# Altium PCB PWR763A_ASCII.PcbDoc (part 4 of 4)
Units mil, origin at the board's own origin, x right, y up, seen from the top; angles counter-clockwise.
Board outline 5000 x 7000 mil, 4 copper layers (Top Layer, Signal Layer 1, Signal Layer 2, Bottom Layer), stack 61.2 mil thick; 559 components, 281 nets, 1477 pads, 685 vias.
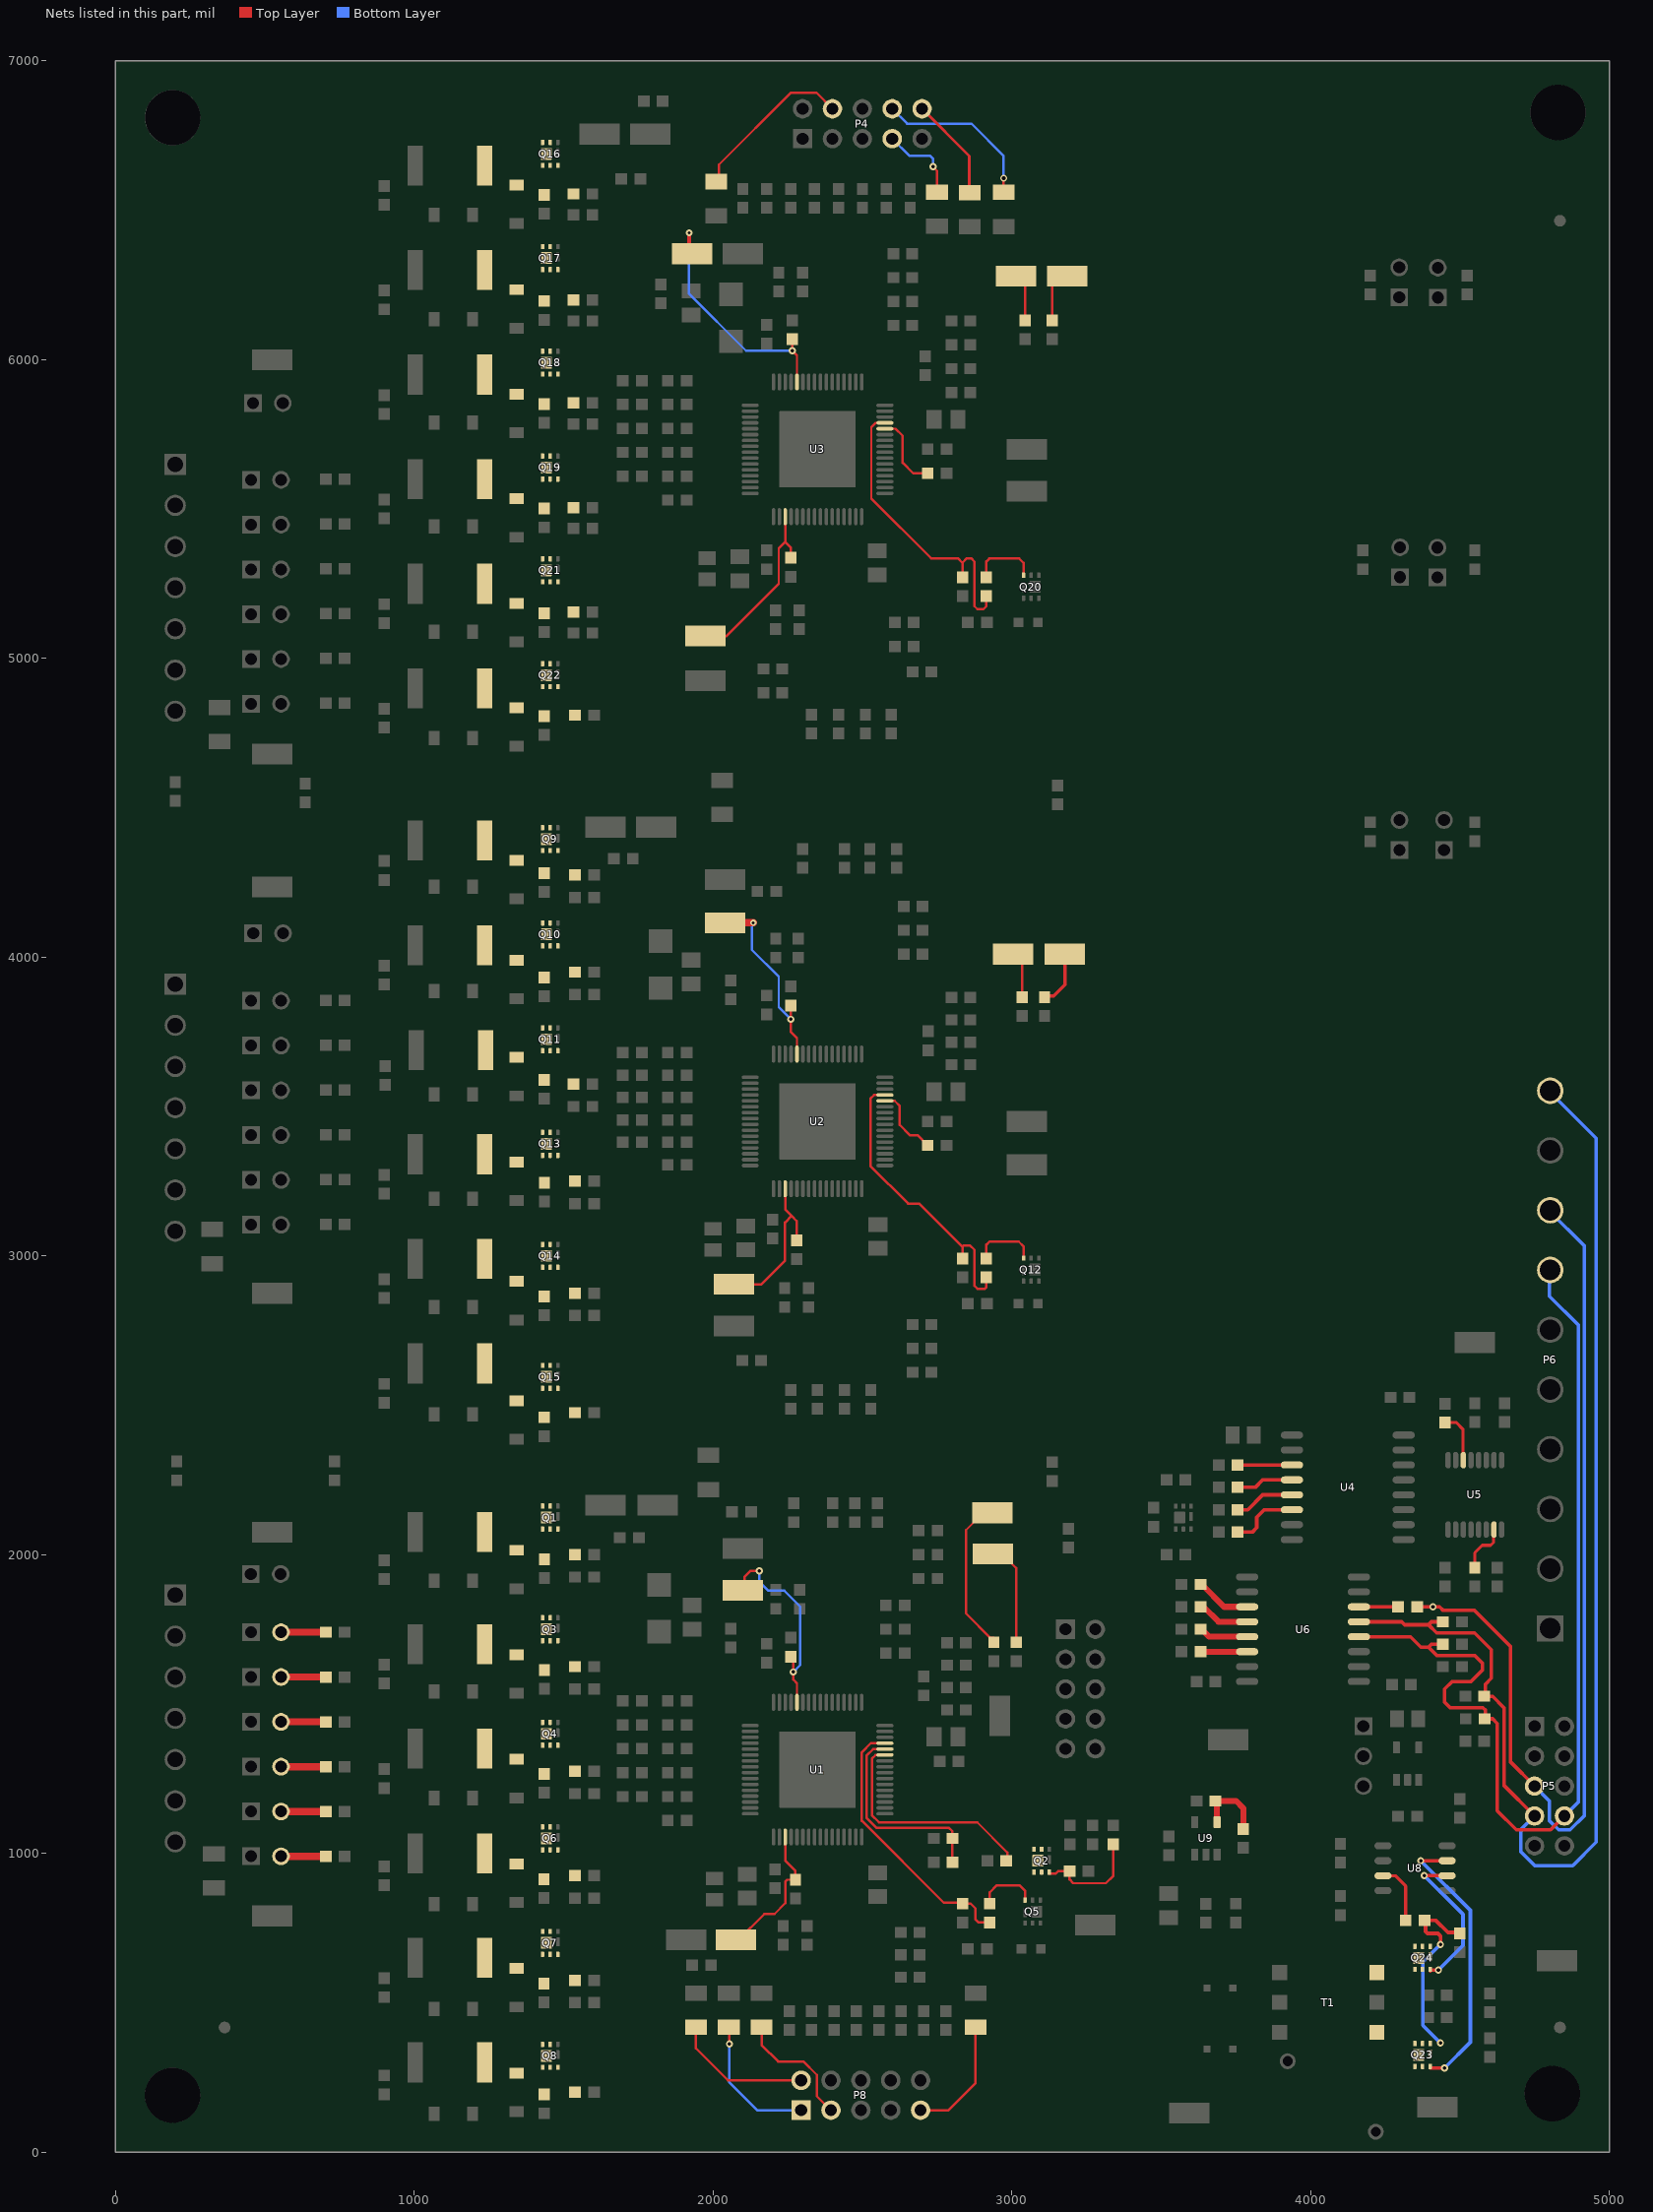
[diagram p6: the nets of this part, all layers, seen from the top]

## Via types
v1: diameter 24, hole 12, Top Layer to Bottom Layer, tented both sides, 607 vias
v2: diameter 19.68, hole 7.87, Top Layer to Bottom Layer, 75 vias
v3: diameter 22, hole 10, Top Layer to Bottom Layer, tented both sides, 3 vias

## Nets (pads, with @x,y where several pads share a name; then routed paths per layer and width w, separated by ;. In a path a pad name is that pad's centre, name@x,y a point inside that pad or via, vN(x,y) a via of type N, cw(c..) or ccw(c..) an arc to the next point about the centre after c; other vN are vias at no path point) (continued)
NetJP13_2: JP13.2 R47.1 | length 144
  Top Layer w24: JP13.2@556,1740 R47.1@700,1740
NetJP14_2: JP14.2 R48.1 | length 144
  Top Layer w24: JP14.2@556,1590 R48.1@700,1590
NetJP15_2: JP15.2 R49.1 | length 144
  Top Layer w24: JP15.2@556,1440 R49.1@700,1440
NetJP16_2: JP16.2 R50.1 | length 144
  Top Layer w24: JP16.2@556,1290 R50.1@700,1290
NetJP17_2: JP17.2 R51.1 | length 144
  Top Layer w24: JP17.2@556,1140 R51.1@700,1140
NetJP18_2: JP18.2 R52.1 | length 144
  Top Layer w24: JP18.2@556,990 R52.1@700,990
NetP4_4: P4.4 R1.2 | length 558.1
  Top Layer w8: R1.2@2020,6597.09 2020,6653 2261,6894 2346,6894 P4.4@2400,6840
NetP4_7: P4.7 R10.2 | length 281.6
  Top Layer w8: v1(2737,6646) 2737,6645 2750,6632 R10.2@2750,6561.09
  Bottom Layer w8: P4.7@2600,6740 2658,6682 2727.24,6682 2737,6672.24 v1(2737,6646)
NetP4_8: P4.8 R12.2 | length 560.8
  Top Layer w8: R12.2@2958.87,6560.9 R12.2@2959.06,6561.08 ; R12.2@2972.87,6559.9 2972.97,6560 v1(2972.97,6607.69)
  Bottom Layer w8: P4.8@2600,6840 2650,6790 2865,6790 2972.97,6682.03 v1(2972.97,6607.69)
NetP4_10: P4.10 R11.2 | length 346.6
  Top Layer w10: P4.10@2700,6840 2858,6682 2858,6561.72 R11.2@2860,6559.72
NetP8_1: P8.1 R55.1 | length 463.8
  Top Layer w8: R55.1@2053,417.4 2055,415.4 v1(2055,362)
  Bottom Layer w8: v1(2055,362) 2055,233 2148,140 P8.1@2295,140
NetP8_2: P8.2 R54.1 | length 467.7
  Top Layer w8: R54.1@1943,418.4 1943,347 2050,240 P8.2@2295,240
NetP8_3: P8.3 R56.1 | length 423.3
  Top Layer w8: R56.1@2163,417.4 2163,358 2218,303 2303,303 2348,258 2348,187 P8.3@2395,140
NetP8_9: P8.9 R65.1 | length 410.6
  Top Layer w8: P8.9@2695,140 2788,140 2879,231 R65.1@2879,419.91
NetQ1_1: Q1.1 Q1.2 Q1.5 Q1.6 Q1.8 R66.1
NetQ1_3: Q1.3 R69.2 R71.2 Z3.1
NetQ2_1: Q2.1 Q2.2 Q2.5 Q2.6 Q2.8 R70.1 U1.43 | length 773.8
  Top Layer w8: U1.43@2578.35,1329.21 2544.21,1329.21 2532,1317 2532,1127 2555.79,1103.21 2884.79,1103.21 2985,1003 R70.1@2985,975
NetQ2_3: Q2.3 R73.2 R75.2 | length 366.4
  Top Layer w8: Q2.3@3125.59,931.69 3146.69,931.69 3155,940 R75.2@3193.5,940 3193.5,912.5 3206,900 3315,900 3340,925 R73.2@3340,1030.5
NetQ3_1: Q3.1 Q3.2 Q3.5 Q3.6 Q3.8 R74.1
NetQ3_3: Q3.3 R76.2 R78.2 Z5.1
NetQ4_1: Q4.1 Q4.2 Q4.5 Q4.6 Q4.8 R81.1
NetQ4_3: Q4.3 R87.2 R90.2 Z7.1
NetQ5_3: Q5.3 R88.1 | length 198.9
  Top Layer w8: R88.1@2926,831.5 2926,869 2949,892 3027,892 3044.41,874.59 Q5.3@3044.41,848.31
NetQ6_1: Q6.1 Q6.2 Q6.5 Q6.6 Q6.8 R93.1
NetQ6_3: Q6.3 R95.2 R97.2 Z9.1
NetQ7_1: Q7.1 Q7.2 Q7.5 Q7.6 Q7.8 R100.1
NetQ7_3: Q7.3 R102.2 R107.2 Z11.1
NetQ8_1: Q8.1 Q8.2 Q8.5 Q8.6 Q8.8 R110.1
NetQ8_3: Q8.3 R111.2 R112.2 Z13.1
NetQ9_1: Q9.1 Q9.2 Q9.5 Q9.6 Q9.8 R113.1
NetQ9_3: Q9.3 R116.2 R117.2 Z16.1
NetQ10_1: Q10.1 Q10.2 Q10.5 Q10.6 Q10.8 R119.1
NetQ10_3: Q10.3 R120.2 R121.2 Z18.1
NetQ11_1: Q11.1 Q11.2 Q11.5 Q11.6 Q11.8 R124.1
NetQ11_3: Q11.3 R125.2 R129.2 Z20.1
NetQ12_3: Q12.3 R130.2 | length 206.2
  Top Layer w8: R130.2@2915,2995 2915,3037.37 2925.38,3047.75 3023.59,3047.75 3039.41,3031.92 3039.41,3003.31
NetQ13_1: Q13.1 Q13.2 Q13.5 Q13.6 Q13.8 R133.1
NetQ13_3: Q13.3 R136.2 R137.2 Z22.1
NetQ14_1: Q14.1 Q14.2 Q14.5 Q14.6 Q14.8 R139.1
NetQ14_3: Q14.3 R142.2 R143.2 Z24.1
NetQ15_1: Q15.1 Q15.2 Q15.5 Q15.6 Q15.8 R147.1
NetQ15_3: Q15.3 R148.2 R149.2 Z26.1
NetQ16_1: Q16.1 Q16.2 Q16.5 Q16.6 Q16.8 R150.1
NetQ16_3: Q16.3 R153.2 R154.2 Z29.1
NetQ17_1: Q17.1 Q17.2 Q17.5 Q17.6 Q17.8 R156.1
NetQ17_3: Q17.3 R157.2 R158.2 Z31.1
NetQ18_1: Q18.1 Q18.2 Q18.5 Q18.6 Q18.8 R160.1
NetQ18_3: Q18.3 R162.2 R163.2 Z33.1
NetQ19_1: Q19.1 Q19.2 Q19.5 Q19.6 Q19.8 R167.1
NetQ19_3: Q19.3 R173.2 R174.2 Z35.1
NetQ20_3: Q20.3 R171.2 | length 220.6
  Top Layer w8: R171.2@2915,5275 2915,5324.41 2925,5334.41 3025,5334.41 3039.41,5320 Q20.3@3039.41,5283.31
NetQ21_1: Q21.1 Q21.2 Q21.5 Q21.6 Q21.8 R176.1
NetQ21_3: Q21.3 R178.2 R180.2 Z37.1
NetQ22_1: Q22.1 Q22.2 Q22.5 Q22.6 Q22.8 R183.1
NetQ22_3: Q22.3 R186.2 R187.2 Z39.1
NetQ23_1: Q23.1 Q23.2 Q23.5 Q23.6 Q23.8 T1.1
NetQ23_3: Q23.3 U8.7 | length 922.3
  Top Layer w12: v1(4369.02,975.07) 4444,975.07 U8.7@4444,975 ; Q23.3@4400.59,281.69 4400.59,280.93 v1(4448.21,280.93)
  Bottom Layer w12: v1(4369.02,975.07) 4535,809.09 4535,367.71 v1(4448.21,280.93)
NetQ23_4: Q23.4 Q23.7 Q24.4 Q24.7 R214.2 R215.2 | length 631.6
  Top Layer w12: v1(4435,695) 4435,723.29 4426.44,731.85 4391.6,731.85 4385,738.45 4385,775 4420,775 4460,735 R215.2@4500,735
  Bottom Layer w12: v1(4435,365) 4376,424 4376,636 v1(4435,695)
NetQ24_1: Q24.1 Q24.2 Q24.5 Q24.6 Q24.8 T1.3
NetQ24_3: Q24.3 U8.6 | length 498.3
  Top Layer w12: v1(4380.63,925.58) 4444,925.58 U8.6@4444,925 ; Q24.3@4400.59,606.69 4400.59,608.93 v1(4428.21,608.93)
  Bottom Layer w12: v1(4380.63,925.58) 4510.48,795.73 4510.48,691.19 v1(4428.21,608.93)
NetR86_1: R86.1 R88.2 U1.45 | length 909.8
  Top Layer w8: U1.45@2575.39,1368.58 2528.58,1368.58 2498,1338 2498,1109 2772,835 2831.5,835 R86.1@2835,831.5 2862.5,831.5 2879,815 2879,778 2888.5,768.5 R88.2@2926,768.5
NetR89_1: R89.1 TP-3.1 U1.19 | length 481.9
  Top Layer w8: TP-3.1@2077,710 2085,710 2172,797 2206,797 2242,833 2242,905 2248.5,911.5 R89.1@2276,911.5 2276,941 2241.73,975.27 U1.19@2241.73,1054.61
NetR91_1: R91.1 TP-1.1 U1.60 | length 695.5
  Top Layer w8: TP-1.1@2105,1885 2105,1925 2125,1945 v1(2155,1945) ; R91.1@2260,1658.5 2269,1649.5 v1(2269,1607) 2269,1581 2281.1,1568.9 U1.60@2281.1,1505.39
  Bottom Layer w8: v1(2155,1945) 2155,1910 2186,1879 2239,1879 2292,1826 2292,1630 v1(2269,1607)
NetR94_1: R94.1 R96.2 U1.44 | length 688.3
  Top Layer w8: U1.44@2575.39,1348.9 2535.9,1348.9 2514,1327 2514,1119 2548.29,1084.71 2790.29,1084.71 2801.5,1073.5 R96.2@2801.5,1050 R94.1@2801.5,970
NetR99_2: R99.2 TP-5.1 | length 496.9
  Top Layer w8: TP-5.1@2900,2140 2900,2135 2847,2082 2847,1803 2929,1721 2940,1721 R99.2@2940,1710
NetR106_2: R106.2 TP-6.1 | length 380.7
  Top Layer w8: TP-6.1@2900,2005 2965,2005 3015,1955 R106.2@3015,1710
NetR126_1: R126.1 R130.1 U2.45 | length 981.3
  Top Layer w8: U2.45@2578.35,3538.58 2539.58,3538.58 2527,3526 2527,3301 2653,3175 2690,3175 2835,3030 ; R126.1@2835,2995 2835,3030 ; R130.1@2915,2925 2915,2895 2910,2890 2885,2890 2875,2900 2875,3020 2860,3035 2840,3035 2835,3030
NetR132_1: R132.1 TP-9.1 U2.19 | length 545.2
  Top Layer w8: TP-9.1@2070,2905 2162.27,2905 2241.14,2983.87 2241.14,3111.62 2263.19,3133.67 ; U2.19@2241.73,3221.65 2241.73,3155.12 2263.19,3133.67 ; R132.1@2280,3055 2280,3116.85 2263.19,3133.67
NetR134_1: R134.1 TP-7.1 U2.60 | length 640.2
  Top Layer w8: R134.1@2260,3835 2260.79,3835 v1(2260.79,3791.93) 2260.79,3749.14 2281.1,3728.82 U2.60@2281.1,3678.35
  Top Layer w24: TP-7.1@2040,4115 v3(2135,4115)
  Bottom Layer w8: v3(2135,4115) 2130,4110 2130,4025 2220,3935 2220,3832.72 v1(2260.79,3791.93)
NetR135_1: R135.1 U2.44 | length 242.3
  Top Layer w8: U2.44@2575.39,3518.9 2608.1,3518.9 2625,3502 2625,3438 2659,3404 2684.5,3404 R135.1@2718.5,3370
NetR140_2: R140.2 TP-11.1 | length 140
  Top Layer w8: R140.2@3035,3870 TP-11.1@3035,4010
NetR144_2: R144.2 TP-12.1 | length 185.7
  Top Layer w12: R144.2@3110,3870 3140,3870 3178,3908 TP-12.1@3178,4010
NetR168_1: R168.1 R171.1 U3.45 | length 1014.3
  Top Layer w8: U3.45@2575.39,5788.58 2545,5788.58 2530,5773.58 2530,5535 2730,5335 2820,5335 2835,5320 ; R168.1@2835,5271.5 2835,5320 ; R171.1@2915,5208.5 2915,5175 2905,5165 2885,5165 2875,5175 2875,5324 2864,5335 2850,5335 2835,5320
NetR169_1: R169.1 TP-15.1 U3.19 | length 605.7
  Top Layer w8: TP-15.1@1975,5075 2045,5075 2220,5250 2220,5368.27 2241.73,5390 ; U3.19@2241.73,5471.65 2241.73,5390 ; R169.1@2260,5340 2260,5371.73 2241.73,5390
NetR170_1: R170.1 TP-13.1 U3.60 | length 846.1
  Top Layer w8: R170.1@2265,6065 v1(2265,6030) 2281.1,6013.9 U3.60@2281.1,5928.35
  Top Layer w12: v3(1920,6425) 1920,6365.75 TP-13.1@1930.75,6355
  Bottom Layer w8: v3(1920,6425) 1920,6220.59 2110.59,6030 v1(2265,6030)
NetR172_1: R172.1 U3.44 | length 257.5
  Top Layer w8: U3.44@2575.39,5768.9 2611.1,5768.9 2635,5745 2635,5655 2670,5620 R172.1@2718.5,5620
NetR179_2: R179.2 TP-17.1 | length 145
  Top Layer w8: R179.2@3045,6135 TP-17.1@3045,6280
NetR184_2: R184.2 TP-18.1 | length 177.4
  Top Layer w8: R184.2@3135,6135 3135,6250 3165,6280 TP-18.1@3185,6280
NetR188_2: R188.2 U4.3 | length 175.6
  Top Layer w12: R188.2@3760,2300 3760.1,2299.9 U4.3@3935.6,2299.9
NetR189_2: R189.2 U4.4 | length 185.9
  Top Layer w12: R189.2@3760,2225 3815.1,2225 3840,2249.9 U4.4@3935.6,2249.9
NetR190_1: R190.1 U5.6 | length 182
  Top Layer w10: R190.1@4450,2442.5 4487.5,2442.5 4510,2420 U5.6@4510,2307.3
NetR193_2: R193.2 U4.5 | length 196.3
  Top Layer w12: R193.2@3760,2150 3790.1,2150 3840,2199.9 U4.5@3935.6,2199.9
NetR194_2: R194.2 U4.6 | length 227.1
  Top Layer w12: R194.2@3760,2075 3805.1,2075 3820.1,2090 3820.1,2125 3845,2149.9 U4.6@3935.6,2149.9
NetR195_1: R195.1 U5.15 | length 174
  Top Layer w10: R195.1@4550,1956.5 4550,2006 4575,2031 4603,2031 4612.3,2040.3 U5.15@4612.3,2088.3
NetR197_1: R197.1 U6.14 | length 156.5
  Top Layer w20: R197.1@3631.5,1675 U6.14@3787.99,1675
NetR201_1: R201.1 U6.13 | length 166.9
  Top Layer w20: R201.1@3631.5,1750 3636,1750 3661,1725 U6.13@3787.99,1725
NetR203_1: R203.1 U6.12 | length 177.2
  Top Layer w20: R203.1@3631.5,1825 3642,1825 3692,1775 U6.12@3787.99,1775
NetR205_2: R205.2 U6.6 | length 131.5
  Top Layer w12: U6.6@4162.01,1825 R205.2@4293.5,1825
NetR206_1: R206.1 U6.11 | length 187.6
  Top Layer w20: R206.1@3631.5,1900 3636,1900 3711,1825 U6.11@3787.99,1825
NetR212_2: R212.2 R213.2 U9.4 | length 244
  Top Layer w20: R212.2@3681.5,1175 3751,1175 3775,1151 R213.2@3775,1081.5 ; R212.2@3687,1175 3687,1104.54 U9.4@3687.4,1104.13
NetR214_1: R214.1 U8.3 | length 193.3
  Top Layer w10: U8.3@4255,925 4284,925 4318.5,890.5 R214.1@4318.5,775
SCLK: P5.7 P6.10 R200.1 R209.2 U6.5 | length 4197.6
  Top Layer w12: U6.5@4164.4,1775.1 4164.5,1775 4305,1775 4315,1765 4395,1765 ; R200.1@4440,1775 4405,1775 4395,1765 ; P5.7@4750,1125 4647.48,1227.52 4647.48,1487.52 4610,1525 4585,1525 4585,1565.86 4605,1585.86 4605,1681.77 4549.27,1737.5 4422.5,1737.5 4395,1765
  Bottom Layer w12: P5.7@4750,1125 4703.5,1078.5 4703.5,1005.74 4750.74,958.5 4877.55,958.5 4956.5,1037.45 4956.5,3393.5 P6.10@4800,3550
SIMO: P5.8 P6.7 R199.1 R208.2 U6.4 | length 3387.4
  Top Layer w12: U6.4@4164.4,1725.1 4164.5,1725 4335,1725 4370,1690 4395,1690 ; R199.1@4440,1700 4405,1700 4395,1690 ; P5.8@4850,1125 4803.5,1078.5 4688.89,1078.5 4625,1142.39 4625,1435 4610,1450 4585,1450 4585,1480 4577.5,1487.5 4467.5,1487.5 4449,1506 4449,1550 4474,1575 4536.77,1575 4576,1614.23 4576,1635.77 4549.27,1662.5 4422.5,1662.5 4395,1690
  Bottom Layer w12: P6.7@4800,2950 4800,2865.25 4896.5,2768.75 4896.5,1171.5 P5.8@4850,1125
SOMI: P5.5 P6.8 R205.1 | length 3222.9
  Top Layer w12: R205.1@4360,1825 v1(4410,1825) 4432.62,1825 4444.62,1813 4548.77,1813 4670,1691.77 4670,1305 P5.5@4750,1225
  Bottom Layer w12: P5.5@4750,1225 4800,1175 4800,1109.24 4830.74,1078.5 4869.26,1078.5 4916.5,1125.74 4916.5,3033.5 P6.8@4800,3150
pads on no net: FID1.1 FID2.1 FID3.1 H1. H2. H3. H4. LBL1.0 P7.3 P7.4 P7.6 SH-J1.0 SH-J2.0 SH-J3.0 SH-J4.0 SH-J5.0 SH-J6.0 SH-J7.0 SH-J8.0 SH-JP1.0 SH-JP2.0 SH-JP3.0 SH-JP4.0 SH-JP5.0 SH-JP6.0 SH-JP7.0 SH-JP8.0 SH-JP9.0 SH-JP10.0 SH-JP11.0 SH-JP12.0 SH-JP13.0 SH-JP14.0 SH-JP15.0 SH-JP16.0 SH-JP17.0 SH-JP18.0 SH-JP19.0 U1.30 U1.31 U1.51 U1.62 U2.30 U2.31 U2.36 U2.37 U2.38 U2.39 U2.40 U2.41 U2.42 U2.43 U2.51 U2.62 U3.30 U3.31 U3.36 U3.37 U3.38 U3.39 U3.40 U3.41 U3.42 U3.43 U3.51 U3.62 U7.4 U8.1
copper on no net: | length 43.5
  Top Layer w20: v1(1805,5450) 1848.5,5450

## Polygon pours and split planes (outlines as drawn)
2-VC0 on Bottom Layer "Bottom-2-VSS" (solid, remove dead copper, pour order 21): 50,4500 50,2300 2250,2300 2250,1475 2629,1475 2629,2300 3250,2300 3400,2450 3400,4500 2650,4500 2650,3625 2250,3625 2250,4500
3-VC0 on Bottom Layer "Bottom-3-VSS" (solid, remove dead copper, pour order 22): 50,6950 50,4575 2275,4575 2275,3650 2625,3650 2625,4575 3390,4575 3390,6950
1-VC0 on Bottom Layer "Bottom-1-VSS" (solid, remove dead copper, pour order 24): 50,2250 50,50 4015,50 4015,2435 3545,2435 3465,2355 3465,2350 3365,2250 2625,2250 2625,1450 2225,1450 2225,2250
2-VC0 on Top Layer "Top-2-VSS" (solid, remove dead copper, pour order 16): 50,4500 50,2300 2250,2300 2250,1475 2600,1475 2600,2300 3400,2300 3400,4500 2650,4500 2650,3625 2250,3625 2250,4500
1-VC0 on Top Layer "Top-1-VSS" (solid, remove dead copper, pour order 19): 50,2250 50,50 4015,50 4015,2435 3545,2435 3465,2355 3465,2350 3365,2250 2625,2250 2625,1450 2225,1450 2225,2250
3-VC0 on Top Layer "Top-3-VSS" (solid, remove dead copper, pour order 18): 50,6950 50,4575 2275,4575 2275,3650 2625,3650 2625,4575 3390,4575 3390,6950
2-VC0 on Signal Layer 1 "Signal Layer 2-No Net 1" (solid, remove dead copper, pour order 20): 50,4500 3400,4500 3400,2450 3250,2300 50,2300
1-VC0 on Signal Layer 1 "Signal Layer 2-No Net 2" (solid, remove dead copper, pour order 23): 50,2250 3400,2250 3400,50 50,50
NetC120_1 on Signal Layer 1 "Signal Layer 2-No Net 3" (solid, remove dead copper, pour order 25): 3460,2350 3545,2435 4010,2435 4010,50 3460,50 3460,2325
3.3_SW on Signal Layer 1 "Signal Layer 2-No Net 4" (solid, remove dead copper, pour order 26): 4075,2990 4675,2990 4675,3725 4965,3725 4965,50 4065,50 4065,2990
AGND on Signal Layer 1 "Signal Layer 2-No Net" (solid, pour order 17): 50,6950 3390,6950 3390,4580 3385,4575 50,4575
3-VC0 on Signal Layer 2 "Signal Layer 1-No Net" (solid, remove dead copper, pour order 27): 50,6950 3390,6950 3400,6940 3400,4575 2625,4575 2625,3650 2276.77,3650 2276.77,4575 50,4575
2-VC0 on Signal Layer 2 "Signal Layer 1-No Net 1" (solid, remove dead copper, pour order 28): 50,4500 2250,4500 2250,3625 2650,3625 2650,4500 3400,4500 3400,2445 3255,2300 3250,2300 2600,2300 2600,1475 2251.46,1475 2250,1476.46 2250,2300 50,2300
1-VC0 on Signal Layer 2 "Signal Layer 1-No Net 2" (solid, remove dead copper, pour order 29): 50,2250 2200,2250 2225,2250 2225,1450 2625,1450 2625,2250 3365,2250 3545,2430 3545,2435 4015,2435 4015,2370 4015,50 3830,50 50,50
AGND on Signal Layer 2 "Signal Layer 1-No Net 3" (solid, remove dead copper, pour order 30): 4065,2990 4675,2990 4675,3735 4965,3735 4965,35 4065,35 4065,2990 4675,2990 4675,3735 4675,2990

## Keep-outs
Keep-Out Layer:
  text ".Layer_Name" at 577,-858.49 h60

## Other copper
Top Layer:
  text ".Layer_Name" at 577,-858.49 h60
Signal Layer 1:
  text ".Layer_Name" at 577,-858.49 h60
Signal Layer 2:
  text ".Layer_Name" at 577,-858.49 h60
Bottom Layer:
  text ".Layer_Name" at 577,-858.49 h60

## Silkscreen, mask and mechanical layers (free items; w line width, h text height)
Top Overlay:
  lines w5: 1615,3679 1655,3639 ; 1620,5700 1642,5722 1642,5733 1655,5746 ; 1624,3637 1642,3619 1642,3593 1649,3586 1649,3559 1656,3552 ; 1630,5655 1660,5684
  lines w6: 1626,5936 1627,5936 1644,5919 1644,5867 1660,5851 ; 2563,626 2581,608 2590,608
  lines w8: 3010,5035 3030,5035 ; 3020,2710 3040,2710 ; 3025,560 3045,560 ; 3065,5005 3065,5035 ; 3065,5065 3065,5035 ; 3075,2680 3075,2710 ; 3075,2740 3075,2710 ; 3080,530 3080,560 ; 3080,590 3080,560 ; 3100,5035 3065,5035 ; 3110,2710 3075,2710 ; 3115,560 3080,560 ; 4019.6,58.56 4019.6,1033.56 ; 4019.6,1233.56 4019.6,2833.56 ; 4049.6,58.56 4049.6,1033.56 ; 4070,1235 4070,2835 ; 4635,3005 4635,3685 ; 3065,5035 3035,5005 3035,5065 3065,5035 ; 3075,2710 3045,2680 3045,2740 3075,2710 ; 3080,560 3050,530 3050,590 3080,560
  lines w10: 1515,2255 820,2255 820,40 2065,40 ; 1525,4505 1480,4505 820,4505 820,2295 1515,2295 1870,2295 ; 1700,6895 818.3,6895 818.3,4570.8 1919.2,4570.8 ; 1885,6895 2055,6895 ; 2065,2255 2235,2255 ; 2065,2295 3035,2295 ; 2105,4500 3050,4500 ; 2105,4575 3050,4575 ; 2590,2255 3035,2255 ; 2920,40 3400,40 3400,1080 ; 3020,6900 3400,6900 3400,4575.8 3205.8,4575.8 ; 3178.89,2250 3200,2250 3400,2250 3400,2005 ; 3180,2295 3399.2,2295 ; 3205,4500 3400,4500 3400,2445 3400,2294.2 ; 4965,40 3425,40 3425,3005 4630,3005 4630,3690 4965,3690 ; 4000,4015 4800,4015 4800,4665 4000,4665 4000,4015 ; 4000,4880 4800,4880 4800,5530 4000,5530 4000,4880 ; 4000,5750 4800,5750 4800,6425 4000,6425 4000,5750
  text "2" at 2062.56,6837.64 h25
  text "10" at 2917.27,6834.64 h25
  text "9" at 2921.77,6735.68 h25
  text "1" at 2070.06,6720.68 h25
  text "Bq76PL536A-Q1 EVM-3" at 3618,6549 h100
  text "PWR763A" at 4195,6440 h100
  text "TS2+" at 2190,6340 h45
  text "TS2-" at 1730,6335 h45
  text "CAUTION" at 245,6260 h100
  text "HIGH VOLTAGE" at 117,6149 h100
  text "JUMPERS" at 130,5995 h50
  text "THERMISTORS CIRCUIT 3" at 4065,5980 h40
  text "THERMISTORS" at 4145,5790 h50
  text "1" at 195.7,5776.01 h50
  text "CELL 18+" at 292,5658 h35
  text "CELL 17+" at 291,5509 h35
  text "CELL 16+" at 291,5359 h35
  text "CELL 15+" at 290,5210 h35
  text "THERMISTORS CIRCUIT 2" at 4060,5070 h40
  text "TS1-" at 1785,5065 h45
  text "CELL 14+" at 291,5058 h35
  text "TS1+" at 1780,4910 h45
  text "THERMISTORS" at 4140,4910 h50
  text "CELL 13+" at 293,4908 h35
  text "CIRCUIT 3" at 2930,4720 h50
  text "CELL 13-" at 625,4695 h35
  text "7" at 182.2,4643.89 h50
  text "TIPMM-21246-01" at 3639.73,4570.85 h50 r90
  text "JUMPERS" at 115,4390 h50
  text "TS2+" at 1845,4240 h45
  text "THERMISTORS CIRCUIT 1" at 4065,4195 h40
  text "TS2-" at 1850,4170 h45
  text "CELL 12+" at 625,4080 h35
  text "THERMISTORS" at 4170,4045 h50
  text "1" at 191.38,4030.83 h50
  text "CELL 12+" at 290,3930 h35
  text "CELL 11+" at 290,3765 h35
  text "10" at 4755.64,3747.19 h37.5
  text "CELL 10+" at 290,3615 h35
  text "CELL 9+" at 290,3465 h35
  text "CELL 8+" at 290,3315 h35
  text "CELL 7+" at 290,3165 h35
  text "TIPMM-21246-01" at 3593,3040 h50
  text "CELL 7-" at 440,2995 h35
  text "7" at 185.2,2904.48 h50
  text "TS1-" at 1860,2880 h45
  text "ISOLATED COMMUNICATIONS INTERFACE" at 3520,2870 h35
  text "TS1+" at 1865,2775 h45
  text "COMMS" at 3720,2515 h50
  text "CIRCUIT 2" at 2935,2470 h50
  text "JUMPERS" at 105,2140 h50
  text "TS2+" at 1905,2005 h45
  text "1" at 197.2,1994.3 h50
  text "2" at 3324,1985 h37.5
  text "1" at 3086,1982 h37.5
  text "CELL 6+" at 620,1915 h35
  text "TS2-" at 1905,1895 h45
  text "CELL 6+" at 267,1793 h35
  text "1" at 4635,1650 h37.5
  text "1" at 4940,1650 h37.5
  text "CELL 5+" at 267,1643 h35
  text "CELL 4+" at 268,1498 h35
  text "CELL 3+" at 269,1350 h35
  text "CELL 2+" at 269,1201 h35
  text "10" at 3445,1160 h37.5
  text "3.3V" at 3985,1160 h35
  text "9" at 3010,1155 h37.5
  text "H" at 2700,1110 h37.5
  text "5.0V" at 3985,1095 h35
  text "CELL 1+" at 269,1051 h35
  text "CELL 1-" at 420,880 h35
  text "S" at 2685,865 h37.5
  text "7" at 192.7,860.68 h50
  text "9" at 4701.34,744.9 h37.5
  text "10" at 4873,744 h37.5
  text "TS1-" at 1723.17,694.09 h45
  text "TS1+" at 2191.7,602.68 h45
  text "10" at 2930,295 h25
  text "2" at 2010,285 h25
  text "CIRCUIT 1" at 2975,155 h50
  text "9" at 2945,95 h25
  text "1" at 2010,85 h25
  text ".Layer_Name" at 577,-858.49 h60
Bottom Overlay:
  text ".Layer_Name" at 577,-858.49 h60
Top Paste:
  text ".Layer_Name" at 577,-858.49 h60
Bottom Paste:
  text ".Layer_Name" at 577,-858.49 h60
Top Solder:
  the board outline again, w30
  text ".Layer_Name" at 577,-858.49 h60
  text ".Layer_Name" at 577,-858.49 h60
Bottom Solder:
  the board outline again, w30
  text ".Layer_Name" at 577,-858.49 h60
Drill Guide:
  text ".Layer_Name" at 577,-858.49 h60
M1 Board Outline:
  lines w10: 5000,40 5000,3690 ; 0,0 0,7000 5000,7000 5000,0 0,0
  text ".Layer_Name" at 577,-858.49 h60
M2 Board Dimensions:
  rectangle: 0,-275 125,-150
  rectangle: 125,-400 500,-275
  lines w7: 0,-275 1000,-275 ; 125,-400 125,-150 ; 250,-400 250,-150 ; 500,-400 500,-150 ; 750,-400 750,-150 ; 0,-400 1000,-400 1000,-150 0,-150 0,-400
  text ".Layer_Name" at 577,-858.49 h60
M3 3D STEP Top:
  text ".Layer_Name" at 577,-858.49 h60
M4 3D STEP Bottom:
  text ".Layer_Name" at 577,-858.49 h60
M5 Assembly Top:
  lines w10: -292,-930.17 6308,-930.17 ; -292,-726.83 6310,-726.83 ; -292,-523.5 -292,-1133.5 3713,-1133.5 6310,-1133.5 6310,-523.5 -291.5,-523.5 -291.5,-1133.5 1284,-1133.5 ; 2173,-1133.5 2173,-523.5 ; 3440,-726.83 3440,-523.5 ; 4280,-726.83 4280,-523.5 ; 4902,-1140 4902,-937.17
  text "COMPONENTS MARKED 'DNP' SHOULD NOT BE POPULATED." at 1153.5,-318.5 h60
  text "ASSEMBLY VARIANT:" at 1153,-434 h60
  text ".VariantName" at 2189,-434 h60
  text "PCB VIEWED FROM TOP SIDE" at -228.5,-655.67 h60
  text "BOARD #:" at 2248,-655.67 h60
  text ".PRJ_Number" at 2793.5,-655.67 h60
  text "REV:" at 3638,-655.67 h60
  text ".PCB_Rev" at 3929.5,-655.67 h60
  text "SVN REV:" at 4476,-655.67 h60
  text ".VersionControl_RevNumber" at 4982,-655.67 h60
  text "TID #:" at 2248,-859 h60
  text ".TID" at 2793.5,-859 h60
  text "PLOT NAME =" at -228.5,-1064.34 h60
  text ".plot_File_Name" at 577,-1064.34 h60
  text "GENERATED    :" at 2250,-1064.34 h60
  text ".Print_Date" at 3119.5,-1064.34 h60
  text ".Print_Time" at 3848.5,-1064.34 h60
  text "TEXAS INSTRUMENTS" at 5113,-1064.34 h60
M6 Assembly Bottom:
  lines w10: -292.5,-727.33 6309.5,-727.33 ; -290.5,-930.67 6309.5,-930.67 ; 1115.5,-1140.5 1115.5,-937.67 ; 1737.5,-727.33 1737.5,-524 ; 2577.5,-727.33 2577.5,-524 ; 3844.5,-1134 3844.5,-524 ; 4733.5,-1134 6309,-1134 6309,-524 -292.5,-524 -292.5,-1134 2304.5,-1134 6309.5,-1134 6309.5,-524
  text "COMPONENTS MARKED 'DNP' SHOULD NOT BE POPULATED." at 6102,-318 h60
  text ".VariantName" at 5058,-434 h60
  text "ASSEMBLY VARIANT:" at 6097,-434 h60
  text ".VersionControl_RevNumber" at 1035.5,-656.17 h60
  text "SVN REV:" at 1541.5,-656.17 h60
  text ".PCB_Rev" at 2088,-656.17 h60
  text "REV:" at 2379.5,-656.17 h60
  text ".PRJ_Number" at 3224,-656.17 h60
  text "BOARD #:" at 3769.5,-656.17 h60
  text "PCB VIEWED FROM BOTTOM SIDE" at 6246,-656.17 h60
  text ".PRJ_Number" at 3224,-859.5 h60
  text "TID #:" at 3769.5,-859.5 h60
  text "TEXAS INSTRUMENTS" at 904.5,-1064.84 h60
  text ".Print_Time" at 2169,-1064.84 h60
  text ".Print_Date" at 2898,-1064.84 h60
  text "GENERATED    :" at 3767.5,-1064.84 h60
  text ".plot_File_Name" at 5440.5,-1064.84 h60
  text "PLOT NAME =" at 6246,-1064.84 h60
M9 Title Sheet:
  lines w10: -491.5,1041.5 -291.5,1041.5 ; -491.5,3416.5 -291.5,3416.5 ; -491.5,5791.5 -291.5,5791.5 ; 2008.5,-1333.5 2008.5,-1133.5 ; 2008.5,7966.5 2008.5,8166.5 ; 4508.5,-1333.5 4508.5,-1133.5 ; 4508.5,7966.5 4508.5,8166.5 ; 6321,-1133.5 6321,-523.5 11303.5,-523.5 ; 7008.5,-1333.5 7008.5,-1133.5 ; 7008.5,7966.5 7008.5,8166.5 ; 9508.5,-1333.5 9508.5,-1133.5 ; 9508.5,7966.5 9508.5,8166.5 ; 11303.5,-1133.5 11303.5,-523.5 ; 11303.5,-823.5 14303.5,-823.5 ; 11303.5,-223.5 14303.5,-223.5 ; 11304.5,370.5 14304.5,370.5 ; 12008.5,-1333.5 12008.5,-1133.5 ; 12008.5,7966.5 12008.5,8166.5 ; 12808.5,-1123.5 12808.5,-523.5 ; 14303.5,-523.5 11303.5,-523.5 ; 14303.5,76.5 11303.5,76.5 ; 14308.5,66.5 14308.5,-1133.5 ; 14308.5,871 11304.5,871 11303.5,871 11303.5,370.5 11303.5,76.5 ; 14308.5,1041.5 14508.5,1041.5 ; 14308.5,3416.5 14508.5,3416.5 ; 14308.5,5791.5 14508.5,5791.5 ; 11303.5,-523.5 11303.5,76.5 ; 14308.5,-1133.5 14308.5,7966.5 -291.5,7966.5 -291.5,-1133.5 14308.5,-1133.5 ; -491.5,-1333.5 -491.5,8166.5 14508.5,8166.5 14508.5,-1333.5 -491.5,-1333.5
  text "1" at 739.84,8036.5 h70
  text "2" at 3235.5,8036.5 h70
  text "3" at 5724.84,8036.5 h70
  text "4" at 8231.51,8036.5 h70
  text "5" at 10730.5,8036.5 h70
  text "6" at 13235.5,8036.5 h70
  text "A" at -416.5,6893.5 h70
  text "A" at 14383.5,6893.5 h70
  text "B" at -416.5,4513.5 h70
  text "B" at 14383.5,4513.5 h70
  text "C" at -416.5,2138.5 h70
  text "C" at 14383.5,2138.5 h70
  text "PROJECT TITLE:" at 11343.5,277.5 h45
  text ".PRJ_Title" at 11393.5,144.17 h60
  text "DESIGNED FOR:" at 11343.5,-23.5 h45
  text ".PRJ_Customer" at 11393.5,-163.5 h60
  text "D" at -416.5,-231.5 h70
  text "D" at 14383.5,-231.5 h70
  text "FILE NAME:" at 11343.5,-323.5 h45
  text ".PCB_File_Name_No_Path" at 11393.5,-443.5 h60
  text "Texas Instruments (TI) and/or its licensors do not warrant the accuracy or completeness of this specification" at 6374,-605.34 h45
  text "ENGINEER:" at 11343.5,-613.5 h45
  text "LAYOUT BY:" at 12848.5,-613.5 h45
  text "or any information contained therein. TI and/or its licensors do not warrant that this design will meet" at 6329.01,-718 h45
  text ".PRJ_Engineer" at 11393.5,-768.49 h60
  text ".PCB_Layout" at 12899,-768.49 h60
  text "the specifications, will be suitable for your application or fit for any particular purpose, or will operate in" at 6329.01,-830.67 h45
  text ".Layer_Name" at 577,-858.49 h60
  text "ALTIUM DESIGNER VERSION:" at 12848.5,-923.5 h45
  text "an implementation. TI and/or its licensors do not warrant that the design is production worthy. You should" at 6329.01,-943.33 h45
  text "completely validate and test your design implementation to confirm the system functionality for your application." at 6374,-1056 h45
  text ".print_Scale" at 11393.5,-1056.83 h70
  text ".Application_BuildNumber" at 12899,-1056.83 h70
  text "1" at 739.84,-1263.5 h70
  text "2" at 3235.5,-1263.5 h70
  text "3" at 5724.84,-1263.5 h70
  text "4" at 8231.51,-1263.5 h70
  text "5" at 10730.5,-1263.5 h70
  text "6" at 13235.5,-1263.5 h70
M10 Fab Notes:
  drawing of 185 lines, arcs and shapes, not listed
  text "DESIGN INFORMATION" at 12381.02,5910 h60
  text "MIN. TRACK WIDTH:" at 11736.46,5730 h60
  text "8" at 12832.7,5730 h60
  text "MIL" at 12987.46,5730 h60
  text "MIN. CLEARANCE:" at 11736.46,5598 h60
  text "0.2" at 12772.7,5598 h60
  text "mm" at 12987.46,5598 h60
  text "MIN. VIA PAD SIZE:" at 11736.46,5466 h60
  text "24" at 12802.71,5466 h60
  text "MIL" at 12987.46,5466 h60
  text "0.05mm (2MIL)" at 12431.46,5324.29 h60
  text "MINIMUM ANNULAR RING" at 11407.23,5320 h60
  text "EXTERNAL" at 13139.46,5320 h60
  text "PER" at 11607.23,5202 h60
  text "IPC-D-275 CLASS 2 LEVEL C" at 11827.23,5202 h60
  text "MIL, HOLES" at 13315.46,5089.71 h60
  text "+/-" at 12923,5089 h60
  text "+/-" at 13777,5089 h60
  text "REGISTRATION TOLERANCES:" at 11407.23,5084 h60
  text "METAL" at 12607,5084 h60
  text "5" at 13183.2,5084 h60
  text "3" at 14016.2,5084 h60
  text "MIL" at 14132.46,5084 h60
  text "MATERIAL:" at 11332.46,4874.54 h60
  text "FR-4 High Tg" at 12318.9,4734.21 h60
  text "FR-408" at 11753.46,4725.64 h60
  text "X" at 12165.46,4725.64 h60
  text "OTHER" at 13241.46,4725.64 h60
  text "62 MIL (1.6mm) +/-10%" at 12073.56,4562.92 h60
  text "X" at 13231,4561 h60
  text "THICKNESS:" at 11407.23,4558.64 h60
  text "OTHER" at 13358.46,4558.64 h60
  text "TOLERANCE:" at 11407.23,4400.64 h60
  text "X" at 12246.53,4400.64 h60
  text "ANSI IPC-6012 TYPE 3 CLASS 2" at 12433.48,4400.64 h60
  text "OTHER +/-" at 12433.46,4244.64 h60
  text "BOW & TWIST:" at 11407.23,4087.64 h60
  text "X" at 12246.53,4087.64 h60
  text "ANSI IPC-6012 TYPE 3 CLASS 2" at 12433.48,4087.64 h60
  text "OTHER +/-" at 12433.46,3929.13 h60
  text "DRILLING:" at 11332.46,3790.64 h60
  text "REFERENCE:" at 11407.23,3673.64 h60
  text "X" at 12055.46,3673.64 h60
  text "AS SHOWN" at 12242.46,3673.64 h60
  text "X" at 12956.46,3673.64 h60
  text "NC_DRILL FILES" at 13093.46,3673.64 h60
  text "X" at 12760,3523 h60
  text "PTH MIN COPPER THICKNESS:" at 11407.23,3515.64 h60
  text "1MIL" at 12894.46,3515.64 h60
  text "OTHER" at 13391.46,3515.64 h60
  text "BOARD FINISH:" at 11332.46,3356.64 h60
  text "SILKSCREEN:" at 11487.68,3238.64 h60
  text "X" at 12436.46,3238.64 h60
  text "TOP" at 12562.46,3238.64 h60
  text "BOTTOM" at 13073.46,3238.64 h60
  text "SILKSCREEN COLOR:" at 11487.68,3071.64 h60
  text "X" at 12435.42,3071.64 h60
  text "WHITE" at 12562.46,3071.64 h60
  text "OTHER" at 13073.46,3071.64 h60
  text "SOLDER RESIST COLOR:" at 11487.68,2901.64 h60
  text "X" at 12055.42,2742.44 h60
  text "GREEN" at 12182.46,2742.44 h60
  text "BLUE" at 12773.46,2742.44 h60
  text "OTHER" at 13311.46,2742.44 h60
  text "IMMERSION GOLD (ENIG)" at 12393.46,2553.92 h60
  text "ENEPIG" at 13731,2550.64 h60
  text "SURFACE FINISH:" at 11332.46,2549.64 h60
  text "X" at 12206.51,2549.64 h60
  text "IMM. TIN/SILVER OR EQUIV" at 11662,2392.64 h60
  text "OTHER" at 13093.46,2392.64 h60
  text "ARRAY/PANEL:" at 11332.46,2213.64 h60
  text "CUT AND TRIM PER MECH LAYER 1" at 12393.46,2209.35 h60
  text "N.C. ROUTE" at 12393.46,2057.64 h60
  text "X" at 13072.46,2057.64 h60
  text "V. SCORE" at 13259.46,2057.64 h60
  text "CERTIFICATION:" at 11332.46,1920.64 h60
  text "MATERIALS AND WORKMANSHIP FOR ALL PCBS" at 12057.46,1920.64 h60
  text "TO MEET OR EXCEED THE REQUIREMENTS OF:" at 12057.46,1822.64 h60
  text "X" at 11683.96,1686.13 h60
  text "ANSI IPC-A-600F CLASS ->" at 11822.96,1686.13 h60
  text "X" at 13462.02,1686.13 h60
  text "2" at 13580.96,1686.14 h60
  text "1" at 13265.96,1684.64 h60
  text "3" at 13934.96,1684.64 h60
  text "X" at 11686.02,1526.64 h60
  text "UL 94V-0" at 11822.96,1526.64 h60
  text "X" at 12498.02,1526.64 h60
  text "RoHS" at 12634.96,1526.64 h60
  text "OTHER" at 13279.36,1526.64 h60
  text "PER ORDER" at 13676.42,1526.64 h60
  text "ADDITIONAL REQUIREMENTS:" at 11332.46,1385.64 h60
  text "MICROSECTION:" at 11407.23,1270.64 h60
  text "YES" at 12312.96,1270.64 h60
  text "REQUIRED" at 13174.46,1114.49 h60
  text "BARE BOARD ELEC. TEST:" at 11407.23,1111.64 h60
  text "NONE" at 12712.96,1111.64 h60
  text "X" at 13047.46,1111.64 h60
  text "PER ORDER" at 13766.46,1111.64 h60
  text "MANUFACTURER'S UL:" at 11407.23,954.64 h60
  text "RAIL" at 12572.96,950.35 h60
  text "METAL" at 13064.77,950.35 h60
  text "X" at 13440,950 h60
  text "SILK" at 13576.46,950.35 h60
  text ".Layer_Name" at 577,-858.49 h60
M11 Gerber Information:
  lines w10: -292,-930.17 6308,-930.17 ; -292,-726.83 6310,-726.83 ; -292,-523.5 -292,-1133.5 3713,-1133.5 6310,-1133.5 6310,-523.5 -291.5,-523.5 -291.5,-1133.5 1284,-1133.5 ; 2173,-1133.5 2173,-523.5 ; 3440,-726.83 3440,-523.5 ; 4280,-726.83 4280,-523.5 ; 4902,-1140 4902,-937.17
  text "ALL ARTWORK VIEWED FROM TOP SIDE" at -228.5,-655.67 h60
  text "BOARD #:" at 2248,-655.67 h60
  text ".PRJ_Number" at 2793.5,-655.67 h60
  text "REV:" at 3638,-655.67 h60
  text ".PCB_Rev" at 3929.5,-655.67 h60
  text "SVN REV:" at 4476,-655.67 h60
  text ".VersionControl_RevNumber" at 4982,-655.67 h60
  text "LAYER NAME =" at -228.5,-858.49 h60
  text "TID #:" at 2248,-859 h60
  text ".TID" at 2793.5,-859 h60
  text "PLOT NAME =" at -228.5,-1064.34 h60
  text ".plot_File_Name" at 577,-1064.34 h60
  text "GENERATED    :" at 2250,-1064.34 h60
  text ".Print_Date" at 3119.5,-1064.34 h60
  text ".Print_Time" at 3848.5,-1064.34 h60
  text "TEXAS INSTRUMENTS" at 5113,-1064.34 h60
M12 Stackup:
  drawing of 269 lines, arcs and shapes, not listed
  text "Layer" at 9465,7585 h60
  text "Name" at 9874.91,7585 h60
  text "Material" at 10814.65,7585 h60
  text "Thickness" at 11674.42,7585 h60
  text "Constant" at 12324.26,7585 h60
  text "Board Layer Stack" at 12894.12,7585 h60
  text "1" at 9465,7465 h60
  text "Top Overlay" at 9874.91,7465 h60
  text "2" at 9465,7345 h60
  text "Top Solder" at 9874.91,7345 h60
  text "Solder Resist" at 10814.65,7345 h60
  text "0.40mil" at 11674.42,7345 h60
  text "3.5" at 12324.26,7345 h60
  text "3" at 9465,7225 h60
  text "Top Layer" at 9874.91,7225 h60
  text "Copper" at 10814.65,7225 h60
  text "2.80mil" at 11674.42,7225 h60
  text "4" at 9465,7105 h60
  text "Dielectric1" at 9874.91,7105 h60
  text "FR-4 High Tg" at 10814.65,7105 h60
  text "8.00mil" at 11674.42,7105 h60
  text "4.8" at 12324.26,7105 h60
  text "5" at 9465,6985 h60
  text "Signal Layer 1" at 9874.91,6985 h60
  text "Copper" at 10814.65,6985 h60
  text "2.80mil" at 11674.42,6985 h60
  text "6" at 9465,6865 h60
  text "Dielectric2" at 9874.91,6865 h60
  text "FR-4 High Tg" at 10814.65,6865 h60
  text "32.00mil" at 11674.42,6865 h60
  text "4.8" at 12324.26,6865 h60
  text "7" at 9465,6745 h60
  text "Signal Layer 2" at 9874.91,6745 h60
  text "Copper" at 10814.65,6745 h60
  text "2.80mil" at 11674.42,6745 h60
  text "8" at 9465,6625 h60
  text "Dielectric3" at 9874.91,6625 h60
  text "FR-4 High Tg" at 10814.65,6625 h60
  text "10.00mil" at 11674.42,6625 h60
  text "4.8" at 12324.26,6625 h60
  text "9" at 9465,6505 h60
  text "Bottom Layer" at 9874.91,6505 h60
  text "Copper" at 10814.65,6505 h60
  text "2.80mil" at 11674.42,6505 h60
  text "10" at 9465,6385 h60
  text "Bottom Solder" at 9874.91,6385 h60
  text "Solder Resist" at 10814.65,6385 h60
  text "0.40mil" at 11674.42,6385 h60
  text "3.5" at 12324.26,6385 h60
  text ".Layer_Name" at 577,-858.49 h60
M13 Component Bodies Top:
  text ".Layer_Name" at 577,-858.49 h60
M14 Component Bodies Bottom:
  text ".Layer_Name" at 577,-858.49 h60
M15 Courtyards Top:
  text ".Layer_Name" at 577,-858.49 h60
M16 Courtyards Bottom:
  text ".Layer_Name" at 577,-858.49 h60
Drill Drawing:
  circle w1: c5735.41,3625.58 r25
  lines w1: 0,7000 0.03,7000 ; 5000,0 5000.03,0 ; 0,0 0.03,0 ; 0,0 0.03,0 ; 0,0 0.03,0 ; 0,0 0.03,0 ; 200,200 200.03,200 200,200 ; 5710.41,3750.58 5735.41,3763.08 5760.41,3750.58 5747.91,3775.58 5760.41,3800.58 5735.41,3788.08 5710.41,3800.58 5722.91,3775.58 5710.41,3750.58 ; 5710.41,3900.58 5710.41,3913.08 5722.91,3925.58 5710.41,3938.08 5710.41,3950.58 5722.91,3950.58 5735.41,3938.08 5747.91,3950.58 5760.41,3950.58 5760.41,3938.08 5747.91,3925.58 5760.41,3913.08 5760.41,3900.58 5747.91,3900.58 5735.41,3913.08 5722.91,3900.58 5710.41,3900.58 ; 5710.41,4063.08 5722.91,4063.08 5735.41,4050.58 5747.91,4063.08 5760.41,4063.08 5747.91,4075.58 5760.41,4088.08 5747.91,4088.08 5735.41,4100.58 5722.91,4088.08 5710.41,4088.08 5722.91,4075.58 5710.41,4063.08 ; 5710.41,4200.58 5760.41,4200.58 5760.41,4250.58 5710.41,4250.58 5710.41,4200.58 ; 5710.41,4375.58 5735.41,4350.58 5760.41,4375.58 5735.41,4400.58 5710.41,4375.58 ; 5710.41,4513.08 5722.91,4513.08 5722.91,4500.58 5747.91,4500.58 5747.91,4513.08 5760.41,4513.08 5760.41,4538.08 5747.91,4538.08 5747.91,4550.58 5722.91,4550.58 5722.91,4538.08 5710.41,4538.08 5710.41,4513.08 ; 5710.41,4650.58 5760.41,4650.58 5760.41,4700.58 5710.41,4700.58 5710.41,4650.58 ; 5720.41,4660.58 5750.41,4660.58 5750.41,4690.58 5720.41,4690.58 5720.41,4660.58
  lines w15: 5642.29,3555.58 9521.26,3555.58 ; 5642.29,4755.58 9521.26,4755.58 ; 6193.17,3405.58 6193.17,4905.58 ; 6890.98,3405.58 6890.98,4905.58 ; 8236.58,3405.58 8236.58,4905.58 ; 8742.46,3405.58 8742.46,4905.58 ; 5642.29,3405.58 9521.26,3405.58 9521.26,4905.58 5642.29,4905.58 5642.29,3405.58
  text "Symbol" at 5732.29,4800.58 h72
  text "Hit Count" at 6238.17,4800.58 h72
  text "Finished Hole Size" at 6935.98,4800.58 h72
  text "Plated" at 8281.58,4800.58 h72
  text "Hole Type" at 8787.46,4800.58 h72
  text "2" at 6238.17,4650.58 h60
  text "33.46mil (0.850mm)" at 6935.98,4650.58 h60
  text "PTH" at 8281.58,4650.58 h60
  text "Round" at 8787.46,4650.58 h60
  text "3" at 6238.17,4500.58 h60
  text "10.00mil (0.254mm)" at 6935.98,4500.58 h60
  text "PTH" at 8281.58,4500.58 h60
  text "Round" at 8787.46,4500.58 h60
  text "4" at 6238.17,4350.58 h60
  text "185.04mil (4.700mm)" at 6935.98,4350.58 h60
  text "NPTH" at 8281.58,4350.58 h60
  text "Round" at 8787.46,4350.58 h60
  text "10" at 6238.17,4200.58 h60
  text "68.90mil (1.750mm)" at 6935.98,4200.58 h60
  text "PTH" at 8281.58,4200.58 h60
  text "Round" at 8787.46,4200.58 h60
  text "21" at 6238.17,4050.58 h60
  text "51.18mil (1.300mm)" at 6935.98,4050.58 h60
  text "PTH" at 8281.58,4050.58 h60
  text "Round" at 8787.46,4050.58 h60
  text "75" at 6238.17,3900.58 h60
  text "7.87mil (0.200mm)" at 6935.98,3900.58 h60
  text "PTH" at 8281.58,3900.58 h60
  text "Round" at 8787.46,3900.58 h60
  text "97" at 6238.17,3750.58 h60
  text "40.00mil (1.016mm)" at 6935.98,3750.58 h60
  text "PTH" at 8281.58,3750.58 h60
  text "Round" at 8787.46,3750.58 h60
  text "607" at 6238.17,3600.58 h60
  text "12.00mil (0.305mm)" at 6935.98,3600.58 h60
  text "PTH" at 8281.58,3600.58 h60
  text "Round" at 8787.46,3600.58 h60
  text "819 Total" at 6238.17,3450.58 h60
  text ".Layer_Name" at 577,-858.49 h60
